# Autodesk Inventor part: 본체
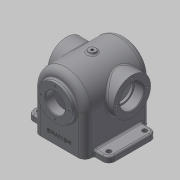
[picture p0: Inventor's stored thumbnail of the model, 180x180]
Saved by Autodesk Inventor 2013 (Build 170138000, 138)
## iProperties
Created: 2019-05
Part Number: 본체
Material: 알루미늄 6061
Document SubType Name: Modeling
Designer: mduedu
Density: 1 g/cm^3
Author: mduedu
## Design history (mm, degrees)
sketch "스케치1"
  geometry: L1 (-55, 0)-(55, 0); L2 (55, 0)-(55, 110); L3 (55, 110)-(-55, 110); L4 (-55, 110)-(-55, 0); 2 further points
  constraints: 8 end point, 2 parallel, 1 coincident, 1 horizontal, 1 midpoint, 1 perpendicular
  dimensions: "d0" = 110 distance of L3.end L1.start; "d2" = 110 distance of L2.end L3.end
extrude "돌출1" new body sketch "스케치1" stored distance "d3" = 86; taper "d4" = 0 deg
fillet "모깎기1"
fillet "모깎기2" dims "d5" = 11
feature "쉘1" dims "d6" = 8
sketch "스케치2"
  geometry: C1 r 29 at (-32, 67); A1 r 43 centre (-32, 67) between (11, 67) and (-75, 67) reference; 1 further point
  constraints: 1 centre point, 1 coincident
  dimensions: "d7" = 58 diameter of C1
extrude "돌출2" join sketch "스케치2" distance "d8" = 7; taper "d9" = 0 deg
fillet "모깎기3" dims "d10" = 3
hole "구멍1" diameter "d13" = 33; stored, may be unused: countersink angle "d17" = 90 deg, drill point angle "d19" = 118 deg; dims "d11" = 10, "d12" = 10, "d14" = 6, "d15" = 4, "d16" = 2, "d18" = 8
node "작업 평면1"
sketch "스케치3"
  geometry: L1 (18, -29)-(18, 29) reference; L2 (-99, 0)-(-99, 32) reference; C1 r 31 at (-56, 0); 2 further points
  constraints: 1 centre point, 1 horizontal alignment, 1 midpoint
  dimensions: "d21" = 62 diameter of C1; "d24" = 43 distance from line of C1.centre L2
extrude "돌출3" join sketch "스케치3" stored distance "d25" = 5; taper "d26" = 0 deg
hole "구멍2" diameter "d29" = 40; stored, may be unused: countersink angle "d33" = 90 deg, drill point angle "d35" = 0 deg; dims "d27" = 10, "d28" = 10, "d30" = 6, "d31" = 4, "d32" = 2, "d34" = 16
hole "구멍3" diameter "d38" = 35; stored, may be unused: countersink angle "d42" = 90 deg, drill point angle "d44" = 0 deg; dims "d36" = 10, "d37" = 10, "d39" = 6, "d40" = 4, "d41" = 2, "d43" = 16
fillet "모깎기4" dims "d45" = 3
chamfer "모따기1" distance "d46" = 1; stored, may be unused: second distance "d47" = 2, angle "d48" = 45 deg
chamfer "모따기2" distance "d49" = 1; stored, may be unused: second distance "d50" = 2, angle "d51" = 45 deg
fillet "모깎기5" dims "d52" = 0.3
node "작업 평면2"
sketch "스케치4"
  geometry: L1 (11, 75)-(11, 11) reference; C1 r 6 at (-44, 43); 1 further point
  constraints: 1 centre point, 1 coincident
  dimensions: "d54" = 12 diameter of C1; "d67" = 55 distance from line of point (-44, 43) L1 (derived)
extrude "돌출4" join sketch "스케치4" stored distance "d55" = 5; taper "d56" = 0 deg
hole "구멍4" diameter "d59" = 4.134; stored, may be unused: countersink angle "d63" = 90 deg, drill point angle "d65" = 0 deg; dims "d57" = 10, "d58" = 10, "d60" = 6, "d61" = 4, "d62" = 2, "d64" = 16
fillet "모깎기6" dims "d66" = 3
sketch "스케치5"
  geometry: L1 (47, -32)-(47, 32) reference; L2 (44, 35)-(-44, 35) reference; L3 (-47, 32)-(-47, -32) reference; L4 (-44, -35)-(44, -35) reference; L5 (-44, -43)-(44, -43) reference; L6 (-55, -32)-(-55, 32) reference; L7 (44, 43)-(-44, 43) reference; L8 (55, 32)-(55, -32) reference; L9 (40, 43)-(-40, 43); L10 (-40, 43)-(-40, 68); L11 (-40, 68)-(40, 68); L12 (40, 68)-(40, 43); A1 r 3 centre (44, -32) between (44, -35) and (47, -32) reference; A2 r 3 centre (44, 32) between (47, 32) and (44, 35) reference; A3 r 3 centre (-44, 32) between (-44, 35) and (-47, 32) reference; A4 r 3 centre (-44, -32) between (-47, -32) and (-44, -35) reference; A5 r 11 centre (44, -32) between (44, -43) and (55, -32) reference; A6 r 11 centre (-44, -32) between (-55, -32) and (-44, -43) reference; A7 r 11 centre (-44, 32) between (-44, 43) and (-55, 32) reference; A8 r 11 centre (44, 32) between (55, 32) and (44, 43) reference; 1 further point
  constraints: 8 end point, 2 parallel, 1 horizontal, 1 perpendicular, 1 point on line
  dimensions: "d68" = 15 distance between parallel lines of L12 L8; "d71" = 80 distance of L10.end L11.end; "d72" = 25 distance between parallel lines of L11 L7
extrude "돌출5" join sketch "스케치5" distance "d73" = 10; taper "d74" = 0 deg
fillet "모깎기7" dims "d76" = 10
sketch "스케치6"
  geometry: L1 (-40, -43)-(-40, -58) reference; L2 (-30, -68)-(30, -68) reference; L3 (40, -58)-(40, -43) reference; L4 (-40, -43)-(40, -43) reference; C1 r 4 at (-30, -58); C2 r 4 at (30, -58); A1 r 10 centre (30, -58) between (30, -68) and (40, -58) reference; A2 r 10 centre (-30, -58) between (-40, -58) and (-30, -68) reference; 1 further point
  constraints: 2 centre point, 2 coincident, 1 equal radius
  dimensions: "d77" = 8 diameter of C1
extrude "돌출6" cut sketch "스케치6" stored distance "d78" = 10; taper "d79" = 0 deg
fillet "모깎기8" dims "d80" = 3
fillet "모깎기9" dims "d81" = 3
fillet "모깎기10" dims "d82" = 3
fillet "모깎기11" dims "d83" = 3
sketch "스케치7"
  geometry: L1 (64, 0)-(0, 0) reference; 4 further points
  constraints: 2 midpoint, 2 vertical alignment, 1 other
  dimensions: "d85" = 15 distance of point (32, 15) point (32, 0)
feature "엠보싱1" sketch "스케치7" dims "d7" = 58, "d86" = 0.5, "d87" = 0
sketch "스케치8"
  geometry: 4 further points
  constraints: 4 other
hole "구멍5" sketch "스케치8" at (0, 24), (-24, 0), (0, -24), (24, 0) diameter "d88" = 3.242; stored, may be unused: countersink angle "d92" = 90 deg, drill point angle "d94" = 120 deg; dims "d89" = 8, "d90" = 4, "d91" = 2, "d93" = 10
sketch "스케치9"
  geometry: 4 further points
  constraints: 4 other
hole "구멍7" sketch "스케치9" at (-26, 0), (0, -26), (26, 0), (0, 26) diameter "d95" = 3.242; stored, may be unused: countersink angle "d99" = 90 deg, drill point angle "d101" = 120 deg; dims "d96" = 8, "d97" = 4, "d98" = 2, "d100" = 10
sketch "스케치10"
  geometry: 4 further points
  constraints: 4 other
hole "구멍9" sketch "스케치10" at (0, -26), (26, 0), (-26, 0), (0, 26) diameter "d102" = 3.242; stored, may be unused: countersink angle "d106" = 90 deg, drill point angle "d108" = 120 deg; dims "d103" = 8, "d104" = 4, "d105" = 2, "d107" = 10
node "솔리드1"
mirror "대칭1"
mirror "대칭2"
node "투영된 루프1"
node "투영된 루프2"
other parameters: "d53" = -113
